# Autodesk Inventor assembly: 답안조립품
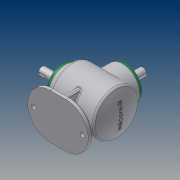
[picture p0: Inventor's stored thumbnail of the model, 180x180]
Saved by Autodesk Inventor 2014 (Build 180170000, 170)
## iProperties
Created: 2016-04
Part Number: 답안조립품
Document SubType Name: Assembly
Designer: owner
Author: owner
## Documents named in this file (14)
- C:\Users\owner\Desktop\460407V1016\답안조립품.iam
- C:\Users\owner\Desktop\460407V1016\메인 축.ipt
- 메인 축.ipt
- C:\Users\owner\Desktop\460407V1016\키 5x5.ipt
- C:\Users\owner\Desktop\460407V1016\커버.ipt
- C:\Users\owner\Desktop\460407V1016\오일실 17 32 8.ipt
- C:\Users\owner\Desktop\460407V1016\베어링 6203.ipt
- C:\Users\owner\Desktop\460407V1016\메인 베벨기어.ipt
- C:\Users\owner\Desktop\460407V1016\본체.ipt
- C:\Users\owner\Desktop\460407V1016\M4.ipt
- C:\Users\owner\Desktop\460407V1016\서브 축.ipt
- 서브 축.ipt
- C:\Users\owner\Desktop\460407V1016\키 4x4.ipt
- C:\Users\owner\Desktop\460407V1016\서브 베벨기어.ipt
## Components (8 placed, 1 different names)
1. M4:1
2. M4:2
3. M4:3
4. M4:4
5. M4:5
6. M4:6
7. M4:7
8. M4:8
## Named parameters: d3_d2 = 0
